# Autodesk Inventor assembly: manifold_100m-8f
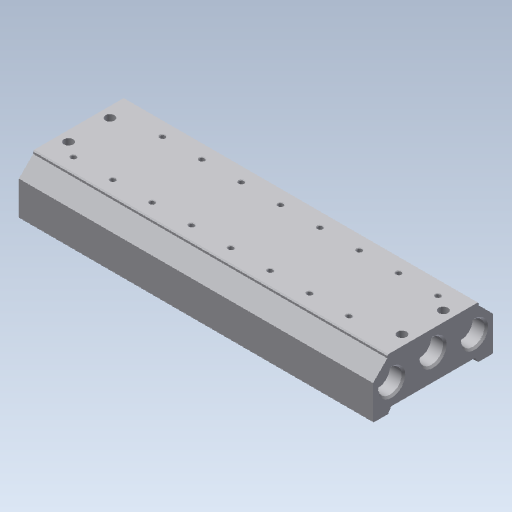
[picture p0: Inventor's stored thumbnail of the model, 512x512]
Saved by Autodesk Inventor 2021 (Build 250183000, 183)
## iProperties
Created: 2021-02
Part Number: manifold_100m-8f
Checked By: TraceParts S.A.
Catalog Web Link: www.traceparts.com
Document SubType Name: Assembly
Designer: TraceParts
Company: TraceParts S.A.
REFERENCE: 100M-8F
DESIGN: Manifold for 4V series solenoid valve 100M-8F
SUPPLIER: ZheJiang XingChen pneumatic Co., LTD
TraceParts.PartNumber: 50-16072015-087160
TraceParts.PartTitle: Manifold for 4V series solenoid valve
TraceParts.InstanceId: 50-16072015-0871609TEDEE2C3QYPV70EKVD1JWSSP
TraceParts.PartStatus: Published
TraceParts.PartVersion: 1.0.8
TRACEPARTS: TRACEPARTS
TraceParts.PartLanguage: en
TraceParts.ClassPath: XINGCHEN_PNEUMATIC:50-16072015-087160
Author: TraceParts
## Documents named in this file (2)
- D:\01 Paralaia\Grupos de Traballo\GT Maquetas\CAD 3D\E_Medida\Electroválvulas\Base 8\manifold_100m-8f.iam
- D:\01 Paralaia\Grupos de Traballo\GT Maquetas\CAD 3D\E_Medida\Electroválvulas\Base 8\manifold_100m-8f_01.ipt
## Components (1 placed, 1 different names)
1. manifold_100m-8f_01:1
